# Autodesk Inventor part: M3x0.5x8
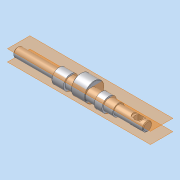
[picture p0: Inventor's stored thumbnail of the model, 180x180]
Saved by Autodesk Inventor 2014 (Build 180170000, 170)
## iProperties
Company: 한국ATC센터
Created: 2009-02
Part Number: M3x0.5x8
Document SubType Name: Modeling
Designer: KYOUNG IL JANG
Density: 7.86 g/cm^3
Mass: 246.092 g
Surface Area: 95.129 cm^2
Volume: 31.3094 cm^3
Material: 강, 연강
Vendor: CBT Solutions
Appearance: 강철
Author: KYOUNG IL JANG
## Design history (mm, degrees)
sketch "스케치1"
  geometry: L1 (-84.5, 0)-(84.5, 0); L2 (-84.5, 0)-(-84.5, 6); L3 (-84.5, 6)-(-30.5, 6); L4 (-30.5, 6)-(-30.5, 9.5); L5 (-30.5, 9.5)-(-15.5, 9.5); L6 (-15.5, 9.5)-(-15.5, 7.5); L7 (-15.5, 7.5)-(46.5, 7.5); L8 (84.5, 6)-(84.5, 0); L9 (34.5, 7.5)-(34.5, 9.5); L10 (34.5, 9.5)-(24.5, 9.5); L11 (24.5, 9.5)-(24.5, 7.5); L12 (46.5, 7.5)-(46.5, 6); L13 (46.5, 6)-(84.5, 6); 2 further points
  constraints: 26 end point, 6 parallel, 6 perpendicular, 2 point on line, 1 coincident, 1 horizontal, 1 midpoint
  dimensions: "d1" = 12 diameter of L3 L1; "d2" = 15 diameter of L7 L1; "d4" = 15 distance of L4.end L5.end; "d5" = 19 diameter of L5 L1; "d24" = 10 distance of L9.end L10.end; "d25" = 19 diameter of L10 L1; "d27" = 40 distance between parallel lines of L11 L6; "d28" = 54 distance of L2.end L3.end; "d29" = 50 distance between parallel lines of L8 L9; "d41" = 38 distance between parallel lines of L8 L12; "d42" = 12 diameter of L13 L1
revolve "회전1" stored, may be unused: angle "d6" = 90 deg
node "작업 평면1"
sketch "스케치2"
  geometry: C1 r 7.5 at (0, 0) reference; C2 r 12.5 at (0, 4.5); 1 further point
  constraints: 1 centre point, 1 vertical alignment
  dimensions: "d8" = 4.5 distance of point (0, 0) C2.centre; "d9" = 25 diameter of C2
extrude "돌출1" join sketch "스케치2" distance "d10" = 18; taper "d11" = 0 deg
chamfer "모따기1" distance "d12" = 1; stored, may be unused: second distance "d13" = 2, angle "d14" = 45 deg
chamfer "모따기2" distance "d15" = 0.5; stored, may be unused: second distance "d16" = 2, angle "d17" = 45 deg
node "작업 평면2"
sketch "스케치3"
  geometry: L1 (4, -2)-(18, -2); L2 (18, 2)-(4, 2); L3 (27, 5)-(27, -5) reference; A1 r 2 centre (18, 0) between (18, -2) and (18, 2); A2 r 2 centre (4, 0) between (4, 2) and (4, -2); 2 further points
  constraints: 4 end point, 4 point on circle, 4 tangent, 2 centre point, 1 horizontal, 1 horizontal alignment, 1 midpoint, 1 parallel
  dimensions: "d18" = 7 distance edge to line of A1 L3; "d19" = 4 distance between parallel lines of L2 L1; "d20" = 18 dimension on A1 A2
extrude "돌출2" cut sketch "스케치3" distance "d21" = 2.5; taper "d22" = 0 deg
revolve "회전2" stored, may be unused: angle "d26" = 90 deg
node "작업 평면3"
sketch "스케치4"
  geometry: L1 (44, 5)-(44, -5) reference; 2 further points
  constraints: 1 horizontal alignment
  dimensions: "d30" = 12 distance from line of point (32, 0) L1
hole "구멍1" sketch "스케치4" at (32, 0) diameter "d31" = 9; stored, may be unused: countersink angle "d35" = 90 deg, drill point angle "d37" = 118 deg; dims "d32" = 6, "d33" = 14, "d34" = 3, "d36" = 8
node "작업 평면4"
sketch "스케치5"
  geometry: C1 r 8 at (32, 0); A1 r 4.5 centre (32, 0) between (29.879, 3.969) and (29.879, -3.969) reference; A2 r 4.5 centre (32, 0) between (34.121, -3.969) and (34.121, 3.969) reference; 1 further point
  constraints: 2 horizontal alignment, 1 centre point, 1 coincident
  dimensions: "d38" = 16 diameter of C1
extrude "돌출3" cut sketch "스케치5" distance "d39" = 3; taper "d40" = 0 deg
node "솔리드1"
node "투영된 루프1"
other parameters: "d7" = 8.5
